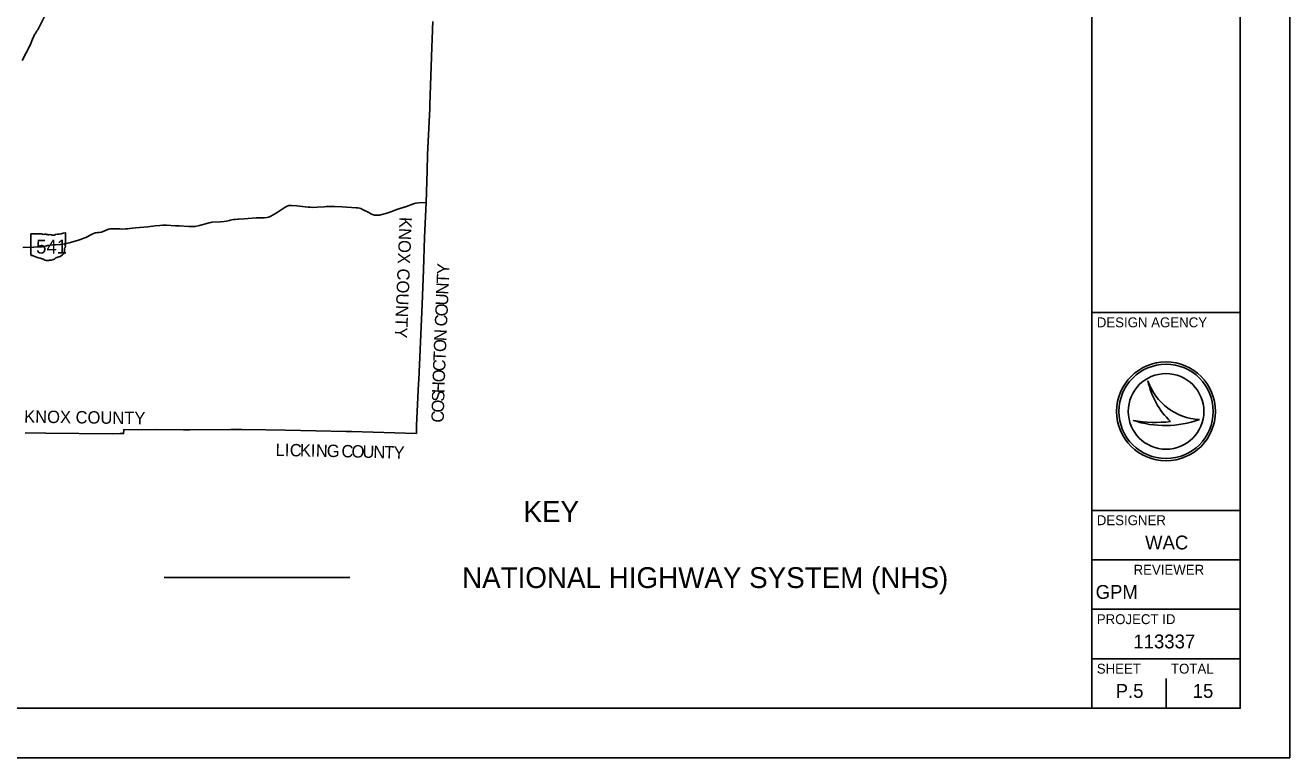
# Model space of a CAD drawing. Extents: x 1851937 to 2123937, y 789467 to 965467.
# Drawn here: x 2021685 to 2123937, y 789467 to 848684 of the extents above; entities that cross this region are included whole.
import ezdxf

# ---------------------------------------------------------------- set-up
doc = ezdxf.new("R2010")
doc.units = 0
for name, color, linetype in [('GM_X_County', 7, 'Continuous'), ('GM_X_County_Text', 7, 'Continuous'), ('GM_X_State_Route', 7, 'Continuous'), ('GM_X_State_Shield', 7, 'Continuous'), ('GM_X_US_Route', 7, 'Continuous'), ('SH_Border', 7, 'Continuous'), ('SH_Cut_Line', 7, 'Continuous'), ('SH_Data', 7, 'Continuous'), ('UT_P_Electric', 7, 'Continuous')]:
    doc.layers.add(name, color=color, linetype=linetype)

msp = doc.modelspace()

# ---------------------------------------------------------------- linework, layer by layer
at = {"layer": 'GM_X_County'}
msp.add_lwpolyline([(2054638, 848994), (2054606, 848369), (2054607, 848277), (2054583, 847562), (2054568, 846927), (2054408, 842255), (2054398, 841945), (2054221, 838228), (2054174, 836926), (2054094, 834355), (2053973, 831537), (2053891, 828875), (2053767, 826144), (2053518, 820007), (2053497, 819709), (2053322, 816320), (2053316, 815692), (2048065, 815838), (2047645, 815846), (2042723, 815938), (2041129, 815964), (2039196, 815994), (2038297, 816009), (2034983, 815969), (2034492, 815973), (2032252, 815993), (2029642, 815987), (2029630, 815668), (2029367, 815674), (2028708, 815664), (2023355, 815717), (2021673, 815746)], dxfattribs=at)
at = {"layer": 'GM_X_State_Route'}
for points in [[(2029952, 832238), (2030108, 832256), (2030346, 832282), (2030597, 832307), (2031592, 832399), (2032180, 832461), (2032572, 832505), (2032800, 832522), (2032958, 832528), (2033117, 832530), (2033841, 832480), (2034136, 832461), (2034924, 832412), (2035163, 832410), (2035426, 832426), (2035761, 832494), (2036549, 832724), (2036702, 832748), (2036773, 832755), (2037484, 832806), (2037755, 832831), (2037951, 832850), (2038057, 832865), (2038195, 832895), (2038244, 832916), (2038536, 832971), (2038663, 832988), (2038861, 833008), (2038943, 833011), (2039387, 833039), (2040347, 833121), (2040792, 833119), (2040992, 833115), (2041217, 833138), (2041356, 833181), (2041442, 833206), (2041535, 833241), (2041735, 833349), (2042051, 833548), (2042460, 833818), (2042620, 833921), (2042711, 833981), (2042802, 834029), (2042869, 834062), (2042946, 834091), (2042980, 834103), (2043026, 834112), (2043117, 834118), (2043221, 834116), (2043634, 834075), (2044325, 834014), (2044549, 833991), (2044751, 833969), (2044931, 833965), (2045285, 833980), (2045854, 834016), (2046037, 834022), (2046308, 834034), (2046496, 834041), (2046698, 834045), (2047274, 834013), (2048444, 833936), (2048591, 833916), (2048718, 833892), (2048815, 833859), (2048914, 833819), (2049105, 833723), (2049296, 833623), (2049459, 833538), (2049642, 833451), (2049753, 833395), (2049838, 833365), (2049936, 833340), (2050041, 833326), (2050246, 833322), (2050341, 833331), (2050634, 833403), (2050835, 833470), (2051332, 833641), (2051649, 833755), (2051987, 833864), (2052501, 834035), (2053071, 834242), (2053272, 834299), (2053515, 834326), (2054095, 834352)], [(2021483, 830726), (2022343, 830751), (2022732, 830765), (2023046, 830784), (2023208, 830800), (2023489, 830872), (2023575, 830891), (2023687, 830908), (2023902, 830930), (2024112, 830941), (2024521, 830974), (2024839, 831012), (2025024, 831043), (2025228, 831086), (2025719, 831239), (2026154, 831378), (2026426, 831471), (2026582, 831537), (2027027, 831764)], [(2027027, 831764), (2027032, 831766), (2027197, 831849), (2027294, 831888), (2027353, 831903), (2027427, 831912), (2027560, 831920), (2027694, 831939), (2027839, 831969), (2028042, 832039), (2028415, 832198), (2028477, 832212), (2028581, 832220), (2028628, 832220), (2028803, 832220)], [(2028803, 832220), (2028974, 832217), (2029145, 832214), (2029319, 832215), (2029475, 832212), (2029785, 832219), (2029952, 832238)]]:
    msp.add_lwpolyline(points, dxfattribs=at)
at = {"layer": 'GM_X_State_Shield'}
for p, q in [((2022147, 831806), (2022147, 830105)), ((2022996, 831836), (2022175, 831836)), ((2024949, 830988), (2024949, 831878)), ((2024949, 830988), (2024949, 830988))]:
    msp.add_line(p, q, dxfattribs=at)
for centre, major_axis, start_param, end_param in [((2022180, 831810), (32.5, 0), 1.7126934, 3.2834897), ((2023191, 832033), (315, 0), 4.042523, 4.731795), ((2023295, 830881), (1130, 0), 1.4047578, 1.6578581), ((2023552, 831819), (90.8, 0), 3.8360951, 5.1854146), ((2023685, 831622), (189, 0), 0.950623, 2.079405), ((2023929, 831892), (227, 0), 4.0815608, 5.1457227), ((2024330, 831316), (598, 0), 1.6990114, 2.1078141), ((2023951, 834155), (2971, 0), 4.8143942, 5.0423688), ((2024918, 831882), (31.2, 0), 6.1411519, 7.9890352), ((2024118, 830502), (743, 0), 5.1017525, 6.4400178), ((2025061, 830616), (211, 0), 2.3877238, 3.2625369), ((2024942, 830923), (48.3, 0), 1.8839779, 3.6710726), ((2024635, 830810), (290, 0), 5.9346948, 6.6959481), ((2024916, 830985), (33.4, 0), 5.05454, 6.4181714), ((2022180, 830102), (32.7, 0), 3.00124, 4.5083009), ((2022185, 830276), (250, 0), 4.6659457, 4.8974612), ((2022236, 830007), (90.1, 0), 0.5192072, 1.6278991), ((2023374, 831536), (2146, 0), 4.1959971, 4.4889607), ((2022734, 829341), (671, 0), 0.8235189, 1.3235874), ((2023460, 829999), (426, 0), 4.0264811, 4.9967352), ((2023706, 829411), (350, 0), 1.495662, 1.9409797), ((2023737, 829871), (227, 0), 4.6910439, 5.5073738), ((2023943, 829707), (63.9, 0), 1.1475842, 2.3151517), ((2023915, 829940), (240, 0), 4.9370686, 5.64225), ((2024431, 829628), (407, 0), 1.6476453, 2.4884337)]:
    msp.add_ellipse(centre, major_axis=major_axis, ratio=0.8, start_param=start_param, end_param=end_param, dxfattribs=at)
at = {"layer": 'GM_X_US_Route'}
msp.add_lwpolyline([(2021421, 845836), (2022068, 847069), (2022278, 847551), (2022403, 847858), (2022439, 847929), (2022474, 847990), (2022532, 848078), (2022629, 848224), (2022689, 848316), (2022742, 848412), (2023222, 849335), (2023604, 850061), (2023662, 850170), (2023711, 850276), (2023758, 850401), (2023790, 850533), (2023809, 850673), (2023817, 850909), (2023831, 851404), (2023837, 851730), (2023865, 853646), (2023864, 853944), (2023857, 854259), (2023844, 854619)], dxfattribs=at)
at = {"layer": 'SH_Border'}
for p, q in [((2107937, 793467), (2107937, 961467)), ((2107937, 825467), (2119937, 825467)), ((2107937, 809467), (2119937, 809467)), ((2107937, 805467), (2119937, 805467)), ((2107937, 801467), (2119937, 801467)), ((2107937, 797467), (2119937, 797467))]:
    msp.add_line(p, q, dxfattribs=at)
msp.add_lwpolyline([(1863937, 961467), (2119937, 961467), (2119937, 793467), (1863937, 793467)], close=True, dxfattribs=at)
at = {"layer": 'SH_Cut_Line'}
msp.add_lwpolyline([(1851937, 789467), (2123937, 789467), (2123937, 965467), (1851937, 965467)], close=True, dxfattribs=at)
at = {"layer": 'SH_Data'}
for p, q in [((2112477, 819944), (2112477, 819944)), ((2113937, 817467), (2113937, 817467)), ((2111275, 816743), (2111275, 816743)), ((2116635, 816815), (2116636, 816815)), ((2113937, 793467), (2113937, 795867)), ((2110937, 794867), (2110937, 794867))]:
    msp.add_line(p, q, dxfattribs=at)
for radius in [4000, 3814, 3814, 3058]:
    msp.add_circle((2113937, 817467), radius, dxfattribs=at)
for centre, radius, start, end in [((2116865, 821448), 4639, 198.92567, 198.93195), ((2118711, 821228), 6365, 191.63793, 191.64215), ((2116865, 821448), 4639, 198.93195, 267.16574), ((2118711, 821228), 6365, 191.64215, 226.09467), ((2113853, 824427), 8105, 251.45764, 290.08324), ((2113121, 826702), 10128, 259.49639, 259.49952), ((2113853, 824427), 8105, 251.45274, 251.45764), ((2113121, 826702), 10128, 259.49952, 276.66723)]:
    msp.add_arc(centre, radius, start, end, dxfattribs=at)
at = {"layer": 'UT_P_Electric'}
msp.add_line((2032926, 804027), (2047926, 804027), dxfattribs=at)

# ---------------------------------------------------------------- texts
at = {"layer": 'GM_X_County_Text'}
for s, rotation, p in [('KNOX COUNTY', 267.71717, (2051952, 833195)), ('Y', 87.57765, (2055969, 828531)), ('T', 87.57747, (2055938, 827783)), ('N', 87.57765, (2055900, 826900)), ('U', 87.57765, (2055863, 826016)), ('C', 87.57735, (2055791, 824319)), ('O', 87.57821, (2055826, 825133)), ('O', 87.58091, (2055704, 822249)), ('N', 87.57873, (2055741, 823132)), ('T', 87.61951, (2055673, 821502)), ('C', 87.73455, (2055641, 820689)), ('O', 87.99332, (2055610, 819806)), ('S', 88.4429, (2055563, 818247)), ('H', 88.14677, (2055581, 818923)), ('O', 88.62214, (2055541, 817364)), ('KNOX COUNTY', 359.20933, (2021587, 816558)), ('C', 88.70029, (2055523, 816550)), ('L', 359.04675, (2041917, 813862)), ('I', 358.96503, (2042663, 813850)), ('C', 358.94354, (2043070, 813842)), ('K', 358.92618, (2043885, 813827)), ('I', 358.92369, (2044767, 813811)), ('N', 358.92127, (2045174, 813803)), ('G', 358.88587, (2046057, 813787)), ('C', 358.71051, (2047244, 813763)), ('O', 358.60959, (2048058, 813745)), ('U', 358.47227, (2048940, 813723)), ('N', 358.42486, (2049822, 813700)), ('T', 358.41862, (2050705, 813676)), ('Y', 358.41862, (2051451, 813655))]:
    msp.add_text(s, height=1000, rotation=rotation, dxfattribs=at).set_placement(p)
at = {"layer": 'GM_X_State_Shield'}
msp.add_text('541', height=1120.7, dxfattribs=at).set_placement((2022560, 830225))
at = {"layer": 'SH_Data'}
for s, height, p in [('DESIGN AGENCY', 800, (2108337, 824267)), ('DESIGNER', 800, (2108337, 808267)), ('WAC', 1120, (2112241, 806307)), ('REVIEWER', 800, (2111312, 804267)), ('GPM', 1120, (2108244, 802307)), ('PROJECT ID', 800, (2108337, 800267)), ('113337', 1120, (2111296, 798307)), ('SHEET', 800, (2108337, 796267)), ('TOTAL', 800, (2114337, 796267)), ('P.5', 1120, (2109863, 794307)), ('15', 1120, (2116095, 794307))]:
    msp.add_text(s, height=height, dxfattribs=at).set_placement(p)
at = {"layer": 'UT_P_Electric'}
for s, p in [('KEY', (2061971, 808535)), ('NATIONAL HIGHWAY SYSTEM (NHS)', (2057006, 803187))]:
    msp.add_text(s, height=1680, dxfattribs=at).set_placement(p)

doc.saveas('drawing.dxf')
